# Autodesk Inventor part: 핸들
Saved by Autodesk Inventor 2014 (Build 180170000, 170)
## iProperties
Created: 2026-09
Part Number: 핸들
Material: 일반
Document SubType Name: Modeling
Designer: dg
Density: 1 g/cm^3
Appearance: 기본값
Author: dg
Author: jhkim
Creation Date: 2026-08-27
Sending System: Autodesk Inventor 2027
Preprocessor: ST-DEVELOPER v20.1
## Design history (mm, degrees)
node "핸들1"
node "솔리드1"
node "기준1"
